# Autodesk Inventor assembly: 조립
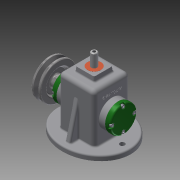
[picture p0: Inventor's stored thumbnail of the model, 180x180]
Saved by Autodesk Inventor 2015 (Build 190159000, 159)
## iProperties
Created: 2017-07
Part Number: 조립
Document SubType Name: Assembly
Designer: Administrator
Author: Administrator
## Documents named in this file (16)
- C:\Users\Administrator\Desktop\470707V1027\조립.iam
- C:\Users\Administrator\Desktop\470707\본체.ipt
- C:\Users\Administrator\Desktop\470707V1027\V벨트풀리.ipt
- C:\Users\Administrator\Desktop\470707V1027\고정핀 1.2 x  8.ipt
- C:\Users\Administrator\Desktop\470707V1027\뒤커버.ipt
- C:\Users\Administrator\Desktop\470707V1027\링크.ipt
- C:\Users\Administrator\Desktop\470707V1027\멈춤나사 M3x8.ipt
- C:\Users\Administrator\Desktop\470707V1027\베어링 12 x 32 x 10.ipt
- C:\Users\Administrator\Desktop\470707V1027\볼트 M4 x 12.ipt
- C:\Users\Administrator\Desktop\470707V1027\부시.ipt
- C:\Users\Administrator\Desktop\470707V1027\슬라이드.ipt
- C:\Users\Administrator\Desktop\470707V1027\앞커버.ipt
- C:\Users\Administrator\Desktop\470707V1027\오일실 12 25 7.ipt
- C:\Users\Administrator\Desktop\470707V1027\키 4 x 4 x 10.ipt
- C:\Users\Administrator\Desktop\470707V1027\편심축.ipt
- C:\Users\Administrator\Desktop\470707V1027\핀 5 x 18.ipt
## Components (3 placed, 3 different names)
1. V벨트풀리:1
2. 고정핀 1.2 x  8:1
3. 핀 5 x 18:1
